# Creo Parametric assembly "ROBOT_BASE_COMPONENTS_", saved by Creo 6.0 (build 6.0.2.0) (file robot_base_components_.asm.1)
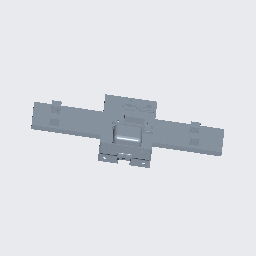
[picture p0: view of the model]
Units: Inch lbm Second (Pro/E Default); INCH, POUND, SECS

Created from: INLBS_ASM_DESIGN.ASM

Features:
  1. datum plane "ASM_RIGHT"
  2. datum plane "ASM_TOP"
  3. datum plane "ASM_FRONT"
  4. coordinate system
  5. component "ROBOT_BASE_", "ROBOT_BASE.PRT"
  6. component "ESP8266_CASE_", "ESP8266_CASE.PRT"
  7. component "ESP8266_CASE_", "ESP8266_CASE.PRT"
  8. component "NANO_CASE2_", "NANO_CASE2.PRT"
  9. component "JETSON_NANO_", "JETSON_NANO.PRT"
  10. component "FUSE_BOX_", "FUSE_BOX.PRT"
  11. component "MOTOR_CONTROLLER_", "MOTOR_CONTROLLER.PRT"
  12. component "MOTOR_CONTROLLER_", "MOTOR_CONTROLLER.PRT"
  13. component "MOTOR_CONTROLLER_", "MOTOR_CONTROLLER.PRT"
  14. component "MOTOR_CONTROLLER_", "MOTOR_CONTROLLER.PRT"
  15. component "ESP8266_", "ESP8266.PRT"
  16. component "ESP8266_", "ESP8266.PRT"
  17. component "XBEE_", "XBEE.PRT"
  18. component "RTK2_", "RTK2.PRT"
  19. component "REALSENSE_CASE2_", "REALSENSE_CASE2.PRT"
